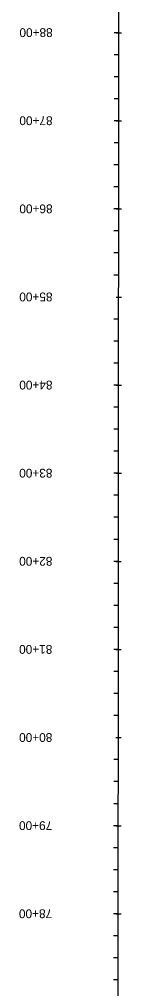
# Model space of a CAD drawing. Extents: x 11526371 to 11527168, y 9590726 to 9599509.
# Drawn here: x 11526431 to 11526546, y 9596222 to 9597322 of the extents above; entities that cross this region are included whole.
import ezdxf

# ---------------------------------------------------------------- set-up
doc = ezdxf.new("R2010")
doc.units = 0
for name, color, linetype in [('Alignment', 7, 'Continuous'), ('Default', 7, 'Continuous'), ('TextAlignmentLrg', 7, 'Continuous'), ('TextAlignmentSml', 7, 'Continuous')]:
    doc.layers.add(name, color=color, linetype=linetype)

msp = doc.modelspace()

# ---------------------------------------------------------------- linework, layer by layer
at = {"layer": 'Alignment'}
for p, q in [((11526542.9, 9596688), (11526544.3, 9599499.3)), ((11526542.5, 9596132.7), (11526542.9, 9596688))]:
    msp.add_line(p, q, dxfattribs=at)
at = {"layer": 'Default'}
msp.add_line((11526542.5, 9596132.7), (11526542.9, 9596688), dxfattribs=at)
at = {"layer": 'TextAlignmentLrg'}
for p, q in [((11526543.2, 9597306.5), (11526537.7, 9597306.5)), ((11526543.1, 9597206.5), (11526537.7, 9597206.5)), ((11526543.1, 9597106.5), (11526537.6, 9597106.5)), ((11526540, 9597006.5), (11526546.1, 9597006.5)), ((11526543, 9596906.5), (11526537.5, 9596906.5)), ((11526542.9, 9596806.5), (11526537.5, 9596806.5)), ((11526542.9, 9596706.5), (11526537.4, 9596706.5)), ((11526542.8, 9596606.5), (11526537.4, 9596606.5)), ((11526539.7, 9596506.5), (11526545.8, 9596506.5)), ((11526542.7, 9596406.5), (11526537.2, 9596406.5)), ((11526542.6, 9596306.5), (11526537.2, 9596306.5))]:
    msp.add_line(p, q, dxfattribs=at)
at = {"layer": 'TextAlignmentSml'}
for p, q in [((11526540.1, 9597306.5), (11526546.2, 9597306.5)), ((11526543.2, 9597281.5), (11526537.7, 9597281.5)), ((11526543.2, 9597256.5), (11526537.7, 9597256.5)), ((11526543.1, 9597231.5), (11526537.7, 9597231.5)), ((11526540.1, 9597206.5), (11526546.2, 9597206.5)), ((11526543.1, 9597181.5), (11526537.7, 9597181.5)), ((11526543.1, 9597156.5), (11526537.6, 9597156.5)), ((11526543.1, 9597131.5), (11526537.6, 9597131.5)), ((11526540, 9597106.5), (11526546.1, 9597106.5)), ((11526543.1, 9597081.5), (11526537.6, 9597081.5)), ((11526543.1, 9597056.5), (11526537.6, 9597056.5)), ((11526543, 9597031.5), (11526537.6, 9597031.5)), ((11526540, 9597006.5), (11526546.1, 9597006.5)), ((11526543, 9596981.5), (11526537.6, 9596981.5)), ((11526543, 9596956.5), (11526537.5, 9596956.5)), ((11526543, 9596931.5), (11526537.5, 9596931.5)), ((11526539.9, 9596906.5), (11526546, 9596906.5)), ((11526543, 9596881.5), (11526537.5, 9596881.5)), ((11526542.9, 9596856.5), (11526537.5, 9596856.5)), ((11526542.9, 9596831.5), (11526537.5, 9596831.5)), ((11526539.9, 9596806.5), (11526546, 9596806.5)), ((11526542.9, 9596781.5), (11526537.5, 9596781.5)), ((11526542.9, 9596756.5), (11526537.4, 9596756.5)), ((11526542.9, 9596731.5), (11526537.4, 9596731.5)), ((11526539.8, 9596706.5), (11526545.9, 9596706.5)), ((11526542.9, 9596681.5), (11526537.4, 9596681.5)), ((11526542.8, 9596656.5), (11526537.4, 9596656.5)), ((11526542.8, 9596631.5), (11526537.4, 9596631.5)), ((11526539.8, 9596606.5), (11526545.9, 9596606.5)), ((11526542.8, 9596581.5), (11526537.3, 9596581.5)), ((11526542.8, 9596556.5), (11526537.3, 9596556.5)), ((11526542.8, 9596531.5), (11526537.3, 9596531.5)), ((11526539.7, 9596506.5), (11526545.8, 9596506.5)), ((11526542.7, 9596481.5), (11526537.3, 9596481.5)), ((11526542.7, 9596456.5), (11526537.3, 9596456.5)), ((11526542.7, 9596431.5), (11526537.3, 9596431.5)), ((11526539.6, 9596406.5), (11526545.8, 9596406.5)), ((11526542.7, 9596381.5), (11526537.2, 9596381.5)), ((11526542.7, 9596356.5), (11526537.2, 9596356.5)), ((11526542.7, 9596331.5), (11526537.2, 9596331.5)), ((11526539.6, 9596306.5), (11526545.7, 9596306.5)), ((11526542.6, 9596281.5), (11526537.2, 9596281.5)), ((11526542.6, 9596256.5), (11526537.2, 9596256.5)), ((11526542.6, 9596231.5), (11526537.1, 9596231.5))]:
    msp.add_line(p, q, dxfattribs=at)

# ---------------------------------------------------------------- texts
at = {"layer": 'TextAlignmentLrg'}
for s, rotation, p in [('85+00', 179.9705, (11526468, 9597011.6)), ('80+00', 179.9666, (11526467.8, 9596511.6))]:
    msp.add_text(s, height=10.02, rotation=rotation, dxfattribs=at).set_placement(p)
at = {"layer": 'TextAlignmentSml'}
for s, rotation, p in [('88+00', 179.9705, (11526468.2, 9597311.6)), ('87+00', 179.9705, (11526468.1, 9597211.6)), ('86+00', 179.9705, (11526468.1, 9597111.6)), ('85+00', 179.9705, (11526468, 9597011.6)), ('84+00', 179.9705, (11526468, 9596911.6)), ('83+00', 179.9705, (11526467.9, 9596811.6)), ('82+00', 179.9705, (11526467.9, 9596711.6)), ('81+00', 179.9666, (11526467.8, 9596611.6)), ('80+00', 179.9666, (11526467.8, 9596511.6)), ('79+00', 179.9666, (11526467.7, 9596411.6)), ('78+00', 179.9666, (11526467.6, 9596311.6))]:
    msp.add_text(s, height=10.02, rotation=rotation, dxfattribs=at).set_placement(p)

doc.saveas('drawing.dxf')
